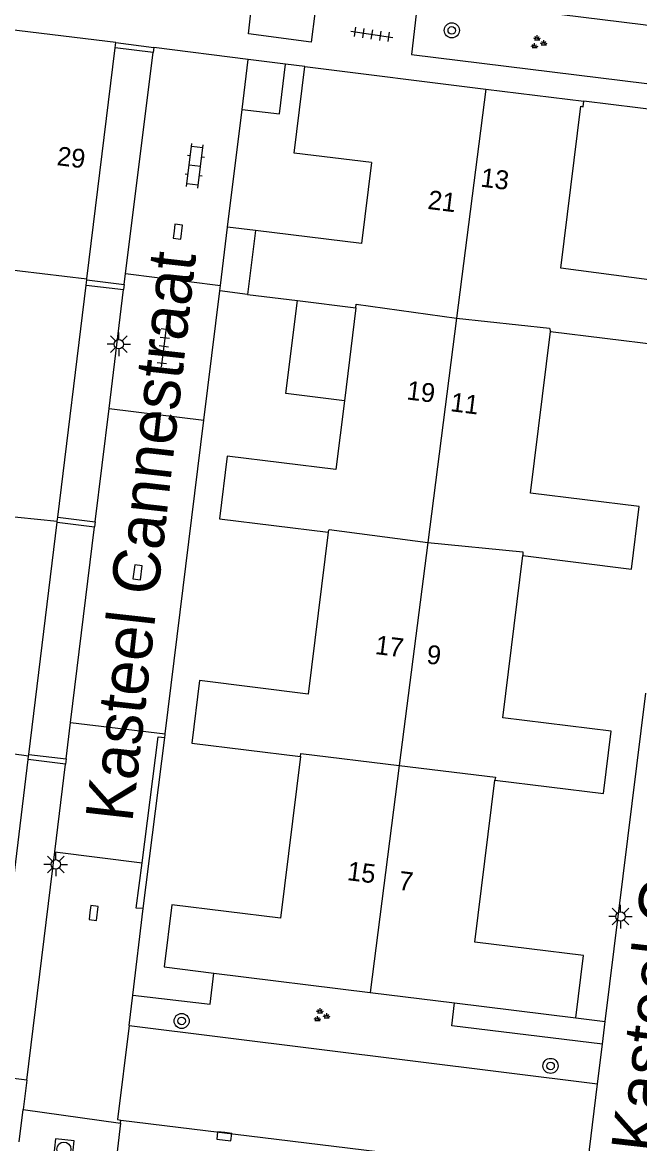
# Model space of a CAD drawing. Extents: x 131000 to 133014, y 396499 to 399001.
# Drawn here: x 131948 to 131980.7, y 396687.1 to 396746.5 of the extents above; entities that cross this region are included whole.
import ezdxf

# ---------------------------------------------------------------- set-up
doc = ezdxf.new("R2010")
doc.units = 0
for name, color, linetype in [('gg-afsc-erfafscheiding', 7, 'Continuous'), ('gg-afsc-muur', 7, 'Continuous'), ('gg-anno-huisnummerreeks BGT', 7, 'Continuous'), ('gg-anno-openbare ruimte label', 7, 'Continuous'), ('gg-bbg-gedigitaliseerde bebouwing', 7, 'Continuous'), ('gg-bbg-hoofdgebouw', 7, 'Continuous'), ('gg-bbg-luifel en loopbrug', 7, 'Continuous'), ('gg-bbg-tussenscheiding', 7, 'Continuous'), ('gg-knt-verharding', 7, 'Continuous'), ('gg-knt-verharding nz', 7, 'Continuous'), ('gt-grn-groengrens', 7, 'Continuous'), ('gt-grn-weggrens', 7, 'Continuous'), ('gt-symb-boom', 7, 'Continuous'), ('gt-symb-groenvak', 7, 'Continuous'), ('gt-symb-klinker verharding', 7, 'Continuous'), ('gt-symb-kolk', 7, 'Continuous'), ('gt-symb-lichtmast', 7, 'Continuous'), ('gt-symb-rioolschacht', 7, 'Continuous'), ('gt-symb-tegel verharding', 7, 'Continuous')]:
    doc.layers.add(name, color=color, linetype=linetype)

# ---------------------------------------------------------------- blocks, each defined once
blk = doc.blocks.new('gt0-BOOM')
at = {"layer": 'gt-symb-boom'}
for radius in [0.4, 0.2]:
    blk.add_circle((0, 0), radius, dxfattribs=at)
blk = doc.blocks.new('gt0-GRVAK')
at = {"layer": 'gt-symb-groenvak'}
for p, q in [((-0.11, 0.189), (-0.228, 0.24)), ((-0.182, 0.153), (0.088, 0.153)), ((-0.091, 0.211), (-0.156, 0.322)), ((-0.047, 0.214), (-0.047, 0.393)), ((-0.004, 0.211), (0.061, 0.322)), ((0.015, 0.189), (0.133, 0.24)), ((0.262, -0.052), (0.197, 0.059)), ((0.305, -0.049), (0.305, 0.13)), ((0.349, -0.052), (0.414, 0.059)), ((-0.245, -0.228), (-0.363, -0.177)), ((-0.318, -0.264), (-0.047, -0.264)), ((-0.226, -0.206), (-0.291, -0.095)), ((-0.183, -0.203), (-0.183, -0.024)), ((-0.139, -0.206), (-0.074, -0.095)), ((-0.12, -0.228), (-0.002, -0.177)), ((0.243, -0.074), (0.125, -0.023)), ((0.17, -0.11), (0.441, -0.11)), ((0.368, -0.074), (0.486, -0.023))]:
    blk.add_line(p, q, dxfattribs=at)
blk = doc.blocks.new('gt0-TEG1')
at = {"layer": 'gt-symb-tegel verharding'}
for p, q in [((-1.125, 0), (1.125, 0)), ((-0.9, -0.25), (-0.9, 0.25)), ((-0.45, -0.25), (-0.45, 0.25)), ((0, -0.25), (0, 0.25)), ((0.45, -0.25), (0.45, 0.25)), ((0.9, -0.25), (0.9, 0.25))]:
    blk.add_line(p, q, dxfattribs=at)
blk = doc.blocks.new('gt0-KL1')
at = {"layer": 'gt-symb-klinker verharding'}
for p, q in [((-1.15, 0.3), (1.15, 0.3)), ((-1, -0.3), (-1, 0.3)), ((-0.5, 0.3), (-0.5, 0.45)), ((0, -0.3), (0, 0.3)), ((0.5, 0.3), (0.5, 0.45)), ((1, -0.3), (1, 0.3)), ((-1.15, -0.3), (1.15, -0.3)), ((-0.5, -0.45), (-0.5, -0.3)), ((0.5, -0.45), (0.5, -0.3))]:
    blk.add_line(p, q, dxfattribs=at)
blk = doc.blocks.new('gt0-LMAST')
at = {"layer": 'gt-symb-lichtmast'}
for p, q in [((-0.005, 0.246), (-0.005, 0.621)), ((-0.182, 0.173), (-0.447, 0.438)), ((0.172, 0.173), (0.437, 0.438)), ((-0.255, -0.004), (-0.63, -0.004)), ((-0.182, -0.181), (-0.447, -0.446)), ((-0.005, -0.254), (-0.005, -0.629)), ((0.437, -0.446), (0.172, -0.181)), ((0.245, -0.004), (0.62, -0.004))]:
    blk.add_line(p, q, dxfattribs=at)
blk.add_circle((-0.005, -0.004), 0.25, dxfattribs=at)
blk = doc.blocks.new('gt0-KOLK')
at = {"layer": 'gt-symb-kolk'}
blk.add_lwpolyline([(0, 0), (0.375, 0), (0.375, 0.4), (-0.375, 0.4), (-0.375, 0), (0, 0)], dxfattribs=at)
blk = doc.blocks.new('gt0-RS')
at = {"layer": 'gt-symb-rioolschacht'}
blk.add_lwpolyline([(-0.5, -0.5), (0.5, -0.5), (0.5, 0.5), (-0.5, 0.5)], close=True, dxfattribs=at)
blk.add_circle((0, 0), 0.375, dxfattribs=at)

msp = doc.modelspace()

# ---------------------------------------------------------------- linework, layer by layer
at = {"layer": 'gg-afsc-erfafscheiding'}
for p, q in [((131958.854, 396735.672), (131959.623, 396741.906)), ((131957.591, 396725.443), (131958.436, 396732.291)), ((131978.852, 396693.607), (131980.989, 396710.987)), ((131977.29, 396693.8), (131978.852, 396693.607))]:
    msp.add_line(p, q, dxfattribs=at)
at = {"layer": 'gg-afsc-muur'}
for p, q in [((131954.909, 396744.924), (131952.897, 396745.172)), ((131952.93, 396745.44), (131954.942, 396745.192)), ((131954.942, 396745.192), (131954.909, 396744.924)), ((131962.95, 396744.171), (131961.922, 396744.301)), ((131984.74, 396741.476), (131977.72, 396742.34)), ((131951.362, 396732.605), (131953.348, 396732.361)), ((131951.395, 396732.873), (131953.381, 396732.629)), ((131953.381, 396732.629), (131953.348, 396732.361)), ((131949.828, 396720.039), (131951.809, 396719.795)), ((131949.861, 396720.307), (131951.842, 396720.062)), ((131951.842, 396720.062), (131951.809, 396719.795)), ((131954.386, 396699.583), (131955.527, 396708.643)), ((131955.527, 396708.643), (131955.544, 396708.779)), ((131950.269, 396707.239), (131948.294, 396707.479)), ((131948.327, 396707.75), (131950.302, 396707.507)), ((131950.302, 396707.507), (131950.269, 396707.239))]:
    msp.add_line(p, q, dxfattribs=at)
at = {"layer": 'gg-bbg-gedigitaliseerde bebouwing'}
msp.add_lwpolyline([(131966.47, 396739.09), (131962.384, 396739.595), (131962.95, 396744.171)], dxfattribs=at)
at = {"layer": 'gg-bbg-hoofdgebouw'}
for p, q in [((131952.93, 396745.44), (131934.02, 396747.77)), ((131951.403, 396732.938), (131952.897, 396745.172)), ((131952.897, 396745.172), (131952.93, 396745.44)), ((131962.95, 396744.171), (131972.519, 396742.98)), ((131972.519, 396742.98), (131977.72, 396742.34)), ((131960.33, 396735.49), (131959.9, 396732.11)), ((131949.861, 396720.307), (131951.362, 396732.605)), ((131951.362, 396732.605), (131951.395, 396732.873)), ((131951.395, 396732.873), (131951.403, 396732.938)), ((131959.9, 396732.11), (131962.552, 396731.783)), ((131962.552, 396731.783), (131965.65, 396731.4)), ((131965.65, 396731.4), (131965.04, 396726.471)), ((131948.327, 396707.75), (131949.828, 396720.039)), ((131949.828, 396720.039), (131949.835, 396720.095)), ((131949.835, 396720.095), (131949.861, 396720.307)), ((131946.791, 396695.174), (131948.294, 396707.479)), ((131948.294, 396707.479), (131948.318, 396707.674)), ((131948.318, 396707.674), (131948.327, 396707.75)), ((131955.5, 396696.49), (131958.131, 396696.165)), ((131958.131, 396696.165), (131966.407, 396695.144)), ((131966.407, 396695.144), (131970.876, 396694.592)), ((131970.876, 396694.592), (131977.29, 396693.8))]:
    msp.add_line(p, q, dxfattribs=at)
for points in [[(131975.95, 396730.15), (131981.7, 396729.44), (131982.11, 396732.75), (131976.49, 396733.5), (131977.55, 396742.07), (131977.68, 396742.05), (131977.72, 396742.34)], [(131966.47, 396739.09), (131965.94, 396734.8), (131960.33, 396735.49)], [(131974.48, 396718.28), (131980.23, 396717.56), (131980.64, 396720.87), (131974.89, 396721.58), (131975.95, 396730.15)], [(131965.04, 396726.471), (131964.59, 396722.83), (131958.84, 396723.54), (131958.43, 396720.23), (131964.18, 396719.52)], [(131964.18, 396719.52), (131963.12, 396710.94), (131957.37, 396711.66), (131956.97, 396708.35), (131962.71, 396707.64)], [(131973.01, 396706.38), (131978.76, 396705.67), (131979.17, 396708.98), (131973.42, 396709.69), (131974.48, 396718.28)], [(131962.71, 396707.64), (131961.65, 396699.07), (131955.91, 396699.78), (131955.5, 396696.49)], [(131977.29, 396693.8), (131977.7, 396697.1), (131971.95, 396697.81), (131973.01, 396706.38)]]:
    msp.add_lwpolyline(points, dxfattribs=at)
at = {"layer": 'gg-bbg-luifel en loopbrug'}
for p, q in [((131959.623, 396741.906), (131959.95, 396744.551)), ((131961.922, 396744.301), (131959.95, 396744.551)), ((131958.473, 396732.588), (131958.854, 396735.672)), ((131960.33, 396735.49), (131958.854, 396735.672)), ((131958.436, 396732.291), (131958.473, 396732.588)), ((131959.9, 396732.11), (131958.436, 396732.291))]:
    msp.add_line(p, q, dxfattribs=at)
for points in [[(131959.623, 396741.906), (131961.596, 396741.662), (131961.922, 396744.301)], [(131965.04, 396726.471), (131961.943, 396726.854), (131962.552, 396731.783)]]:
    msp.add_lwpolyline(points, dxfattribs=at)
at = {"layer": 'gg-bbg-tussenscheiding'}
for p, q in [((131972.519, 396742.98), (131970.969, 396730.849)), ((131945.88, 396733.59), (131951.403, 396732.938)), ((131970.969, 396730.849), (131969.451, 396718.97)), ((131969.451, 396718.97), (131967.942, 396707.162)), ((131942.81, 396708.44), (131948.318, 396707.674)), ((131967.942, 396707.162), (131966.407, 396695.144))]:
    msp.add_line(p, q, dxfattribs=at)
for points in [[(131965.65, 396731.4), (131965.653, 396731.588), (131970.969, 396730.849)], [(131970.969, 396730.849), (131975.906, 396730.325), (131975.95, 396730.15)], [(131944.34, 396721.03), (131944.612, 396720.631), (131949.835, 396720.095)], [(131964.18, 396719.52), (131964.226, 396719.65), (131969.451, 396718.97)], [(131969.451, 396718.97), (131974.494, 396718.474), (131974.48, 396718.28)], [(131962.71, 396707.64), (131962.73, 396707.799), (131967.942, 396707.162)], [(131967.942, 396707.162), (131973.03, 396706.539), (131973.01, 396706.38)]]:
    msp.add_lwpolyline(points, dxfattribs=at)
at = {"layer": 'gg-knt-verharding'}
for p, q in [((131953.452, 396733.208), (131954.909, 396744.924)), ((131959.95, 396744.551), (131954.942, 396745.192)), ((131953.381, 396732.629), (131953.452, 396733.208)), ((131953.452, 396733.208), (131958.473, 396732.588)), ((131952.577, 396726.062), (131953.348, 396732.361)), ((131951.842, 396720.062), (131952.577, 396726.062)), ((131952.577, 396726.062), (131957.591, 396725.443)), ((131955.55, 396708.83), (131957.591, 396725.443)), ((131950.541, 396709.445), (131951.809, 396719.795)), ((131950.302, 396707.507), (131950.541, 396709.445)), ((131955.544, 396708.779), (131955.55, 396708.83)), ((131949.702, 396702.597), (131950.269, 396707.239)), ((131948.219, 396690.494), (131949.702, 396702.597)), ((131953.833, 396694.99), (131954.386, 396699.583)), ((131953.635, 396693.393), (131953.833, 396694.99)), ((131953.635, 396693.393), (131978.446, 396690.305)), ((131978.703, 396692.395), (131978.852, 396693.607)), ((131978.446, 396690.305), (131978.703, 396692.395)), ((131948.219, 396690.494), (131948.028, 396688.938)), ((131947.82, 396687.24), (131948.028, 396688.938)), ((131948.028, 396688.938), (131953.189, 396688.222)), ((131953.189, 396688.222), (131952.372, 396681.419))]:
    msp.add_line(p, q, dxfattribs=at)
for points in [[(131963.671, 396748.514), (131963.279, 396745.468), (131959.955, 396745.904), (131960.3, 396748.947)], [(131968.947, 396747.892), (131968.589, 396744.814), (131984.775, 396742.812), (131985.146, 396745.805)], [(131968.947, 396747.892), (131980.85, 396746.405), (131985.146, 396745.805)], [(131954.324, 396702.015), (131955.184, 396708.686), (131955.527, 396708.643)], [(131954.386, 396699.583), (131954.014, 396699.611), (131954.324, 396702.015)], [(131953.833, 396694.99), (131957.928, 396694.524), (131958.131, 396696.165)], [(131978.703, 396692.395), (131970.726, 396693.381), (131970.876, 396694.592)]]:
    msp.add_lwpolyline(points, dxfattribs=at)
at = {"layer": 'gg-knt-verharding nz'}
for p, q in [((131950.541, 396709.445), (131955.55, 396708.83)), ((131949.702, 396702.597), (131954.324, 396702.015)), ((131953.209, 396688.387), (131977.704, 396685.397))]:
    msp.add_line(p, q, dxfattribs=at)
for points in [[(131953.635, 396693.393), (131953.02, 396688.41), (131953.209, 396688.387)], [(131977.704, 396685.397), (131977.84, 396685.38), (131978.446, 396690.305)]]:
    msp.add_lwpolyline(points, dxfattribs=at)
at = {"layer": 'gt-grn-groengrens'}
msp.add_line((131948.219, 396690.494), (131947.374, 396690.598), dxfattribs=at)
at = {"layer": 'gt-grn-weggrens'}
msp.add_line((131953.189, 396688.222), (131953.209, 396688.387), dxfattribs=at)

# ---------------------------------------------------------------- block references
at = {"layer": 'gt-symb-boom'}
for p in [(131970.724, 396746.092), (131956.422, 396693.631), (131975.953, 396691.252)]:
    msp.add_blockref('gt0-BOOM', p, dxfattribs=at)
at = {"layer": 'gt-symb-groenvak'}
for p in [(131975.291, 396745.439), (131963.795, 396693.916)]:
    msp.add_blockref('gt0-GRVAK', p, dxfattribs=at)
at = {"layer": 'gt-symb-klinker verharding', "rotation": 82.93185994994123}
msp.add_blockref('gt0-KL1', (131957.125, 396738.92), dxfattribs=at)
at = {"layer": 'gt-symb-kolk'}
for p, rotation in [((131956.022, 396735.454), -97.23872650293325), ((131953.888, 396717.414), -97.23872650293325), ((131951.565, 396699.376), -97.23872650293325), ((131958.7, 396687.719), 173.10945167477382)]:
    msp.add_blockref('gt0-KOLK', p, dxfattribs=dict(at, rotation=rotation))
at = {"layer": 'gt-symb-lichtmast'}
for p in [(131953.101, 396729.473), (131949.761, 396701.929), (131979.662, 396699.166)]:
    msp.add_blockref('gt0-LMAST', p, dxfattribs=at)
at = {"layer": 'gt-symb-rioolschacht', "rotation": 83.68511557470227}
msp.add_blockref('gt0-RS', (131950.188, 396686.845), dxfattribs=at)
at = {"layer": 'gt-symb-tegel verharding'}
for p, rotation in [((131966.499, 396745.877), -8.680850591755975), ((131955.483, 396729.371), -97.06814005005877)]:
    msp.add_blockref('gt0-TEG1', p, dxfattribs=dict(at, rotation=rotation))

# ---------------------------------------------------------------- texts
at = {"layer": 'gg-anno-huisnummerreeks BGT'}
for s, rotation, p in [('29', 353.1, (131949.781, 396738.958)), ('13', 352.9, (131972.21, 396737.821)), ('21', 352.9, (131969.414, 396736.64)), ('19', 352.9, (131968.297, 396726.552)), ('11', 352.9, (131970.614, 396725.928)), ('17', 352.9, (131966.63, 396713.068)), ('9', 353, (131969.353, 396712.567)), ('15', 352.9, (131965.148, 396701.097)), ('7', 352.9, (131967.871, 396700.586))]:
    msp.add_text(s, height=1, rotation=rotation, dxfattribs=at).set_placement(p)
at = {"layer": 'gg-anno-openbare ruimte label'}
for p in [(131953.805, 396704.107), (131981.64, 396686.584)]:
    msp.add_text('Kasteel Cannestraat', height=2.5, rotation=83.6, dxfattribs=at).set_placement(p)

doc.saveas('drawing.dxf')
